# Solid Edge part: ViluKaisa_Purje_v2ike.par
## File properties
Author: kaisa
Template: Iso Metric Part.par
Last saved by: kaisa
Revision: 3
Application: Solid Edge
Accuracy: 0.990
Username: kaisa
Face Style: Model Default
Fill Style: Normal
Coef. of Thermal Exp: 0.0
Thermal Conductivity: 0.0
Specific Heat: 0.0
Modulus of Elasticity: 0.0
Poisson's Ratio: 0.0
Yield Stress: 0.0
Ultimate Stress: 0.0
Elongation: 0.0
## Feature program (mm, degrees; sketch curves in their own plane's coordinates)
thicken "Thicken_1"  Distance1 = 0.5 mm
multibody boolean "unnamed MultibodyBoolean 1"
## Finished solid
Body 1: solid body, 6 faces, 4 edges, 0 vertices, 2 separate solids.
  Faces by surface: plane 4, cylinder 2
  Edges by curve: circle 4
Body 2: solid body, 14 faces, 29 edges, 18 vertices, 2 separate solids.
  Faces by surface: spline 8, cylinder 3, offset 2, plane 1
  Edges by curve: intersection 14, curve on surface 9, line 3, spline 3
Body 3: sheet body, 1 face, 4 edges, 4 vertices.
  Faces by surface: spline 1
  Edges by curve: line 2, spline 2
Bounding box of the edges (mm; curved faces can reach further): 11.518 x 150.065 x 200.000, from (-0.8393, -69.4315, -76.7319) to (10.6787, 80.6336, 123.2681).
Cylindrical faces by radius (mm): R1.3393 x3, R3 x2
Planar faces by outward normal: +y 1, +z 1, -y 2, -z 1
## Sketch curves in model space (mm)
line (0, 80.6336, 50.5591) -> (0, 60.4688, -32.5721)
line (0, -69.4315, 51.0904) -> (0, -55.3213, -32.0626)
spline (0, 0, 46.3372) -> (15.8048, 0, -0.6547) -> (10.2734, 0, -43.9829)
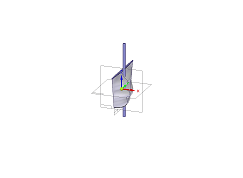
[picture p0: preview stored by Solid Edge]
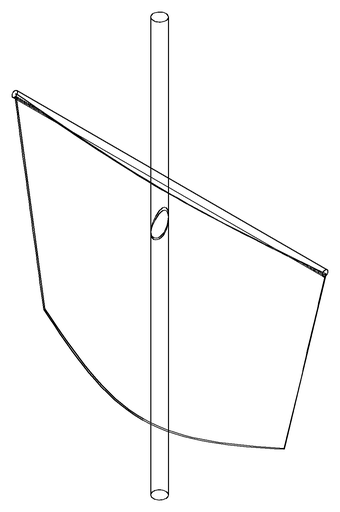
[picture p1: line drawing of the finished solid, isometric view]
